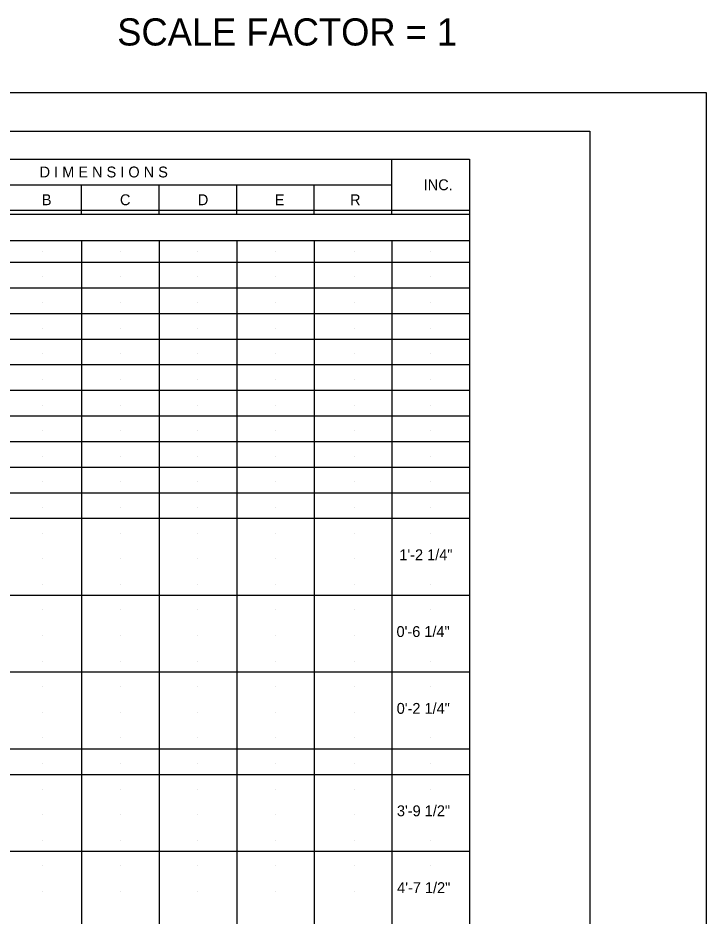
# Model space of a CAD drawing. Extents: x -31.1 to 2.9, y 8.5 to 31.4.
# Drawn here: x -6 to 2.87, y 19.87 to 31.45 of the extents above; entities that cross this region are included whole.
import ezdxf

# ---------------------------------------------------------------- set-up
doc = ezdxf.new("R2010")
doc.units = 0
for name, color, linetype in [('BR_P_Gen_Text', 7, 'Continuous'), ('Default', 7, 'Continuous'), ('SC_Scratch1', 7, 'Continuous')]:
    doc.layers.add(name, color=color, linetype=linetype)

msp = doc.modelspace()

# ---------------------------------------------------------------- linework, layer by layer
at = {"layer": 'BR_P_Gen_Text'}
for p, q in [((-14.678, 29.627), (-0.178, 29.627)), ((-1.178, 28.91), (-1.178, 29.627)), ((-0.178, 29.627), (-0.178, 11.467)), ((-7.178, 29.294), (-1.178, 29.294)), ((-5.178, 28.91), (-5.178, 29.294)), ((-4.178, 28.91), (-4.178, 29.294)), ((-3.178, 28.91), (-3.178, 29.294)), ((-2.178, 28.91), (-2.178, 29.294)), ((-0.178, 28.962), (-14.678, 28.962)), ((-1.523, 28.91), (-14.678, 28.91)), ((-0.178, 28.91), (-14.678, 28.91)), ((-14.678, 28.577), (-0.178, 28.577)), ((-14.678, 28.577), (-0.178, 28.577)), ((-5.178, 28.577), (-5.178, 11.467)), ((-4.178, 28.577), (-4.178, 11.467)), ((-3.178, 28.577), (-3.178, 11.467)), ((-2.178, 28.577), (-2.178, 11.467)), ((-1.178, 28.577), (-1.178, 11.467)), ((-14.678, 28.297), (-0.178, 28.297)), ((-14.678, 28.297), (-0.178, 28.297)), ((-14.678, 27.967), (-0.178, 27.967)), ((-14.678, 27.637), (-0.178, 27.637)), ((-14.678, 27.307), (-0.178, 27.307)), ((-14.678, 26.977), (-0.178, 26.977)), ((-14.678, 26.647), (-0.178, 26.647)), ((-14.678, 26.317), (-0.178, 26.317)), ((-14.678, 25.987), (-0.178, 25.987)), ((-14.678, 25.657), (-0.178, 25.657)), ((-14.678, 25.327), (-0.178, 25.327)), ((-14.678, 24.997), (-0.178, 24.997)), ((-14.678, 24.997), (-0.178, 24.997)), ((-14.678, 24.007), (-0.178, 24.007)), ((-14.678, 23.017), (-0.178, 23.017)), ((-14.678, 22.027), (-0.178, 22.027)), ((-14.678, 22.027), (-0.178, 22.027)), ((-14.678, 21.697), (-0.178, 21.697)), ((-14.678, 21.697), (-0.178, 21.697)), ((-14.678, 21.697), (-0.178, 21.697)), ((-14.678, 20.707), (-0.178, 20.707))]:
    msp.add_line(p, q, dxfattribs=at)
for points in [[(-31.128, 30.484), (2.872, 30.484), (2.872, 8.484), (-31.128, 8.484)], [(-29.128, 29.984), (1.372, 29.984), (1.372, 8.984), (-29.128, 8.984)]]:
    msp.add_lwpolyline(points, close=True, dxfattribs=at)
at = {"layer": 'SC_Scratch1'}
for p, q in [((-5.678, 28.437), (-5.678, 28.437)), ((-5.677, 28.437), (-5.677, 28.437)), ((-4.678, 28.437), (-4.678, 28.437)), ((-4.678, 28.437), (-4.678, 28.437)), ((-3.678, 28.437), (-3.678, 28.437)), ((-3.678, 28.437), (-3.678, 28.437)), ((-2.678, 28.437), (-2.678, 28.437)), ((-2.678, 28.437), (-2.678, 28.437)), ((-1.655, 28.437), (-1.655, 28.437)), ((-1.655, 28.437), (-1.655, 28.437)), ((-0.678, 28.437), (-0.678, 28.437)), ((-0.678, 28.437), (-0.678, 28.437)), ((-5.678, 28.107), (-5.678, 28.107)), ((-5.677, 28.107), (-5.677, 28.107)), ((-4.678, 28.107), (-4.678, 28.107)), ((-4.678, 28.107), (-4.678, 28.107)), ((-3.678, 28.107), (-3.678, 28.107)), ((-3.678, 28.107), (-3.678, 28.107)), ((-2.678, 28.107), (-2.678, 28.107)), ((-2.678, 28.107), (-2.678, 28.107)), ((-1.655, 28.107), (-1.655, 28.107)), ((-1.655, 28.107), (-1.655, 28.107)), ((-0.678, 28.107), (-0.678, 28.107)), ((-0.678, 28.107), (-0.678, 28.107)), ((-5.678, 27.777), (-5.678, 27.777)), ((-5.677, 27.777), (-5.677, 27.777)), ((-4.678, 27.777), (-4.678, 27.777)), ((-4.678, 27.777), (-4.678, 27.777)), ((-3.678, 27.777), (-3.678, 27.777)), ((-3.678, 27.777), (-3.678, 27.777)), ((-2.678, 27.777), (-2.678, 27.777)), ((-2.678, 27.777), (-2.678, 27.777)), ((-1.655, 27.777), (-1.655, 27.777)), ((-1.655, 27.777), (-1.655, 27.777)), ((-0.678, 27.777), (-0.678, 27.777)), ((-0.678, 27.777), (-0.678, 27.777)), ((-5.678, 27.447), (-5.678, 27.447)), ((-5.677, 27.447), (-5.677, 27.447)), ((-4.678, 27.447), (-4.678, 27.447)), ((-4.678, 27.447), (-4.678, 27.447)), ((-3.678, 27.447), (-3.678, 27.447)), ((-3.678, 27.447), (-3.678, 27.447)), ((-2.678, 27.447), (-2.678, 27.447)), ((-2.678, 27.447), (-2.678, 27.447)), ((-1.655, 27.447), (-1.655, 27.447)), ((-1.655, 27.447), (-1.655, 27.447)), ((-0.678, 27.447), (-0.678, 27.447)), ((-0.678, 27.447), (-0.678, 27.447)), ((-5.678, 27.117), (-5.678, 27.117)), ((-5.677, 27.117), (-5.677, 27.117)), ((-4.678, 27.117), (-4.678, 27.117)), ((-4.678, 27.117), (-4.678, 27.117)), ((-3.678, 27.117), (-3.678, 27.117)), ((-3.678, 27.117), (-3.678, 27.117)), ((-2.678, 27.117), (-2.678, 27.117)), ((-2.678, 27.117), (-2.678, 27.117)), ((-1.655, 27.117), (-1.655, 27.117)), ((-1.655, 27.117), (-1.655, 27.117)), ((-0.678, 27.117), (-0.678, 27.117)), ((-0.678, 27.117), (-0.678, 27.117)), ((-5.678, 26.787), (-5.678, 26.787)), ((-5.677, 26.787), (-5.677, 26.787)), ((-4.678, 26.787), (-4.678, 26.787)), ((-4.678, 26.787), (-4.678, 26.787)), ((-3.678, 26.787), (-3.678, 26.787)), ((-3.678, 26.787), (-3.678, 26.787)), ((-2.678, 26.787), (-2.678, 26.787)), ((-2.678, 26.787), (-2.678, 26.787)), ((-1.655, 26.787), (-1.655, 26.787)), ((-1.655, 26.787), (-1.655, 26.787)), ((-0.678, 26.787), (-0.678, 26.787)), ((-0.678, 26.787), (-0.678, 26.787)), ((-5.678, 26.457), (-5.678, 26.457)), ((-5.677, 26.457), (-5.677, 26.457)), ((-4.678, 26.457), (-4.678, 26.457)), ((-4.678, 26.457), (-4.678, 26.457)), ((-3.678, 26.457), (-3.678, 26.457)), ((-3.678, 26.457), (-3.678, 26.457)), ((-2.678, 26.457), (-2.678, 26.457)), ((-2.678, 26.457), (-2.678, 26.457)), ((-1.655, 26.457), (-1.655, 26.457)), ((-1.655, 26.457), (-1.655, 26.457)), ((-0.678, 26.457), (-0.678, 26.457)), ((-0.678, 26.457), (-0.678, 26.457)), ((-5.678, 26.127), (-5.678, 26.127)), ((-5.677, 26.127), (-5.677, 26.127)), ((-4.678, 26.127), (-4.678, 26.127)), ((-4.678, 26.127), (-4.678, 26.127)), ((-3.678, 26.127), (-3.678, 26.127)), ((-3.678, 26.127), (-3.678, 26.127)), ((-2.678, 26.127), (-2.678, 26.127)), ((-2.678, 26.127), (-2.678, 26.127)), ((-1.655, 26.127), (-1.655, 26.127)), ((-1.655, 26.127), (-1.655, 26.127)), ((-0.678, 26.127), (-0.678, 26.127)), ((-0.678, 26.127), (-0.678, 26.127)), ((-5.678, 25.797), (-5.678, 25.797)), ((-5.677, 25.797), (-5.677, 25.797)), ((-4.678, 25.797), (-4.678, 25.797)), ((-4.678, 25.797), (-4.678, 25.797)), ((-3.678, 25.797), (-3.678, 25.797)), ((-3.678, 25.797), (-3.678, 25.797)), ((-2.678, 25.797), (-2.678, 25.797)), ((-2.678, 25.797), (-2.678, 25.797)), ((-1.655, 25.797), (-1.655, 25.797)), ((-1.655, 25.797), (-1.655, 25.797)), ((-0.678, 25.797), (-0.678, 25.797)), ((-0.678, 25.797), (-0.678, 25.797)), ((-5.678, 25.467), (-5.678, 25.467)), ((-5.677, 25.467), (-5.677, 25.467)), ((-4.678, 25.467), (-4.678, 25.467)), ((-4.678, 25.467), (-4.678, 25.467)), ((-3.678, 25.467), (-3.678, 25.467)), ((-3.678, 25.467), (-3.678, 25.467)), ((-2.678, 25.467), (-2.678, 25.467)), ((-2.678, 25.467), (-2.678, 25.467)), ((-1.655, 25.467), (-1.655, 25.467)), ((-1.655, 25.467), (-1.655, 25.467)), ((-0.678, 25.467), (-0.678, 25.467)), ((-0.678, 25.467), (-0.678, 25.467)), ((-5.677, 25.137), (-5.677, 25.137)), ((-4.678, 25.137), (-4.678, 25.137)), ((-3.678, 25.137), (-3.678, 25.137)), ((-2.678, 25.137), (-2.678, 25.137)), ((-1.655, 25.137), (-1.655, 25.137)), ((-0.678, 25.137), (-0.678, 25.137)), ((-5.677, 24.807), (-5.677, 24.807)), ((-4.678, 24.807), (-4.678, 24.807)), ((-3.678, 24.807), (-3.678, 24.807)), ((-2.678, 24.807), (-2.678, 24.807)), ((-1.655, 24.807), (-1.655, 24.807)), ((-0.678, 24.807), (-0.678, 24.807)), ((-5.677, 24.477), (-5.677, 24.477)), ((-4.678, 24.477), (-4.678, 24.477)), ((-3.678, 24.477), (-3.678, 24.477)), ((-2.678, 24.477), (-2.678, 24.477)), ((-1.655, 24.477), (-1.655, 24.477)), ((-0.678, 24.477), (-0.678, 24.477)), ((-5.677, 24.147), (-5.677, 24.147)), ((-4.678, 24.147), (-4.678, 24.147)), ((-3.678, 24.147), (-3.678, 24.147)), ((-2.678, 24.147), (-2.678, 24.147)), ((-1.655, 24.147), (-1.655, 24.147)), ((-0.678, 24.147), (-0.678, 24.147)), ((-5.677, 23.817), (-5.677, 23.817)), ((-4.678, 23.817), (-4.678, 23.817)), ((-3.678, 23.817), (-3.678, 23.817)), ((-2.678, 23.817), (-2.678, 23.817)), ((-1.655, 23.817), (-1.655, 23.817)), ((-0.678, 23.817), (-0.678, 23.817)), ((-5.677, 23.487), (-5.677, 23.487)), ((-4.678, 23.487), (-4.678, 23.487)), ((-3.678, 23.487), (-3.678, 23.487)), ((-2.678, 23.487), (-2.678, 23.487)), ((-1.655, 23.487), (-1.655, 23.487)), ((-0.678, 23.487), (-0.678, 23.487)), ((-5.677, 23.157), (-5.677, 23.157)), ((-4.678, 23.157), (-4.678, 23.157)), ((-3.678, 23.157), (-3.678, 23.157)), ((-2.678, 23.157), (-2.678, 23.157)), ((-1.655, 23.157), (-1.655, 23.157)), ((-0.678, 23.157), (-0.678, 23.157)), ((-5.677, 22.827), (-5.677, 22.827)), ((-4.678, 22.827), (-4.678, 22.827)), ((-3.678, 22.827), (-3.678, 22.827)), ((-2.678, 22.827), (-2.678, 22.827)), ((-1.655, 22.827), (-1.655, 22.827)), ((-0.678, 22.827), (-0.678, 22.827)), ((-5.677, 22.497), (-5.677, 22.497)), ((-4.678, 22.497), (-4.678, 22.497)), ((-3.678, 22.497), (-3.678, 22.497)), ((-2.678, 22.497), (-2.678, 22.497)), ((-1.655, 22.497), (-1.655, 22.497)), ((-0.678, 22.497), (-0.678, 22.497)), ((-5.677, 22.167), (-5.677, 22.167)), ((-4.678, 22.167), (-4.678, 22.167)), ((-3.678, 22.167), (-3.678, 22.167)), ((-2.678, 22.167), (-2.678, 22.167)), ((-1.655, 22.167), (-1.655, 22.167)), ((-0.678, 22.167), (-0.678, 22.167)), ((-5.677, 21.837), (-5.677, 21.837)), ((-4.678, 21.837), (-4.678, 21.837)), ((-3.678, 21.837), (-3.678, 21.837)), ((-2.678, 21.837), (-2.678, 21.837)), ((-1.655, 21.837), (-1.655, 21.837)), ((-0.678, 21.837), (-0.678, 21.837)), ((-5.677, 21.507), (-5.677, 21.507)), ((-4.678, 21.507), (-4.678, 21.507)), ((-3.678, 21.507), (-3.678, 21.507)), ((-2.678, 21.507), (-2.678, 21.507)), ((-1.655, 21.507), (-1.655, 21.507)), ((-0.678, 21.507), (-0.678, 21.507)), ((-5.677, 21.177), (-5.677, 21.177)), ((-4.678, 21.177), (-4.678, 21.177)), ((-3.678, 21.177), (-3.678, 21.177)), ((-2.678, 21.177), (-2.678, 21.177)), ((-1.655, 21.177), (-1.655, 21.177)), ((-0.678, 21.177), (-0.678, 21.177)), ((-5.677, 20.847), (-5.677, 20.847)), ((-5.677, 20.847), (-5.677, 20.847)), ((-4.678, 20.847), (-4.678, 20.847)), ((-4.678, 20.847), (-4.678, 20.847)), ((-3.678, 20.847), (-3.678, 20.847)), ((-2.678, 20.847), (-2.678, 20.847)), ((-1.655, 20.847), (-1.655, 20.847)), ((-0.678, 20.847), (-0.678, 20.847)), ((-5.677, 20.517), (-5.677, 20.517)), ((-5.677, 20.517), (-5.677, 20.517)), ((-4.678, 20.517), (-4.678, 20.517)), ((-4.678, 20.517), (-4.678, 20.517)), ((-3.678, 20.517), (-3.678, 20.517)), ((-2.678, 20.517), (-2.678, 20.517)), ((-1.655, 20.517), (-1.655, 20.517)), ((-0.678, 20.517), (-0.678, 20.517)), ((-5.677, 20.187), (-5.677, 20.187)), ((-5.677, 20.187), (-5.677, 20.187)), ((-4.678, 20.187), (-4.678, 20.187)), ((-4.678, 20.187), (-4.678, 20.187)), ((-3.678, 20.187), (-3.678, 20.187)), ((-2.678, 20.187), (-2.678, 20.187)), ((-1.655, 20.187), (-1.655, 20.187)), ((-0.678, 20.187), (-0.678, 20.187))]:
    msp.add_line(p, q, dxfattribs=at)

# ---------------------------------------------------------------- texts
at = {"layer": 'BR_P_Gen_Text'}
msp.add_text('SCALE FACTOR = 1   ', height=0.35, rotation=360, dxfattribs=at).set_placement((-4.719, 31.09))
for s, p in [('1\'-2 1/4"', (-1.082, 24.457)), ('0\'-6 1/4"', (-1.118, 23.467)), ('0\'-2 1/4"', (-1.116, 22.477)), ('3\'-9 1/2"', (-1.113, 21.157)), ('4\'-7 1/2"', (-1.11, 20.167))]:
    msp.add_text(s, height=0.14, dxfattribs=at).set_placement(p)
at = {"layer": 'Default'}
for s, p in [('D I M E N S I O N S', (-5.72, 29.39)), ('INC.', (-0.768, 29.225)), ('B', (-5.691, 29.032)), ('C', (-4.684, 29.032)), ('D', (-3.68, 29.032)), ('E', (-2.688, 29.032)), ('R', (-1.718, 29.032))]:
    msp.add_text(s, height=0.14, dxfattribs=at).set_placement(p)

doc.saveas('drawing.dxf')
